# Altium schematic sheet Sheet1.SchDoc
size A4
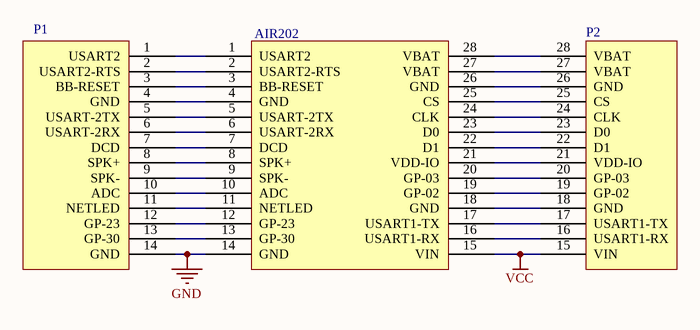
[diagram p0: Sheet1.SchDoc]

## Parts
AIR202  AIR202  [AIR202]  (value not drawn)
P1  P1  [P1]  (value not drawn)
P2  P2  (value not drawn)

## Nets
GND: AIR202.14(GND) P1.14(GND)
VCC: AIR202.15(VIN) P2.15(VIN)
NetAIR202_1: AIR202.1(USART2) P1.1(USART2)
NetAIR202_2: AIR202.2(USART2-RTS) P1.2(USART2-RTS)
NetAIR202_3: AIR202.3(BB-RESET) P1.3(BB-RESET)
NetAIR202_4: AIR202.4(GND) P1.4(GND)
NetAIR202_5: AIR202.5(USART-2TX) P1.5(USART-2TX)
NetAIR202_6: AIR202.6(USART-2RX) P1.6(USART-2RX)
NetAIR202_7: AIR202.7(DCD) P1.7(DCD)
NetAIR202_8: AIR202.8(SPK+) P1.8(SPK+)
NetAIR202_9: AIR202.9(SPK-) P1.9(SPK-)
NetAIR202_10: AIR202.10(ADC) P1.10(ADC)
NetAIR202_11: AIR202.11(NETLED) P1.11(NETLED)
NetAIR202_12: AIR202.12(GP-23) P1.12(GP-23)
NetAIR202_13: AIR202.13(GP-30) P1.13(GP-30)
NetAIR202_16: AIR202.16(USART1-RX) P2.16(USART1-RX)
NetAIR202_17: AIR202.17(USART1-TX) P2.17(USART1-TX)
NetAIR202_18: AIR202.18(GND) P2.18(GND)
NetAIR202_19: AIR202.19(GP-02) P2.19(GP-02)
NetAIR202_20: AIR202.20(GP-03) P2.20(GP-03)
NetAIR202_21: AIR202.21(VDD-IO) P2.21(VDD-IO)
NetAIR202_22: AIR202.22(D1) P2.22(D1)
NetAIR202_23: AIR202.23(D0) P2.23(D0)
NetAIR202_24: AIR202.24(CLK) P2.24(CLK)
NetAIR202_25: AIR202.25(CS) P2.25(CS)
NetAIR202_26: AIR202.26(GND) P2.26(GND)
NetAIR202_27: AIR202.27(VBAT) P2.27(VBAT)
NetAIR202_28: AIR202.28(VBAT) P2.28(VBAT)

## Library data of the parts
AIR202 = Component_1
